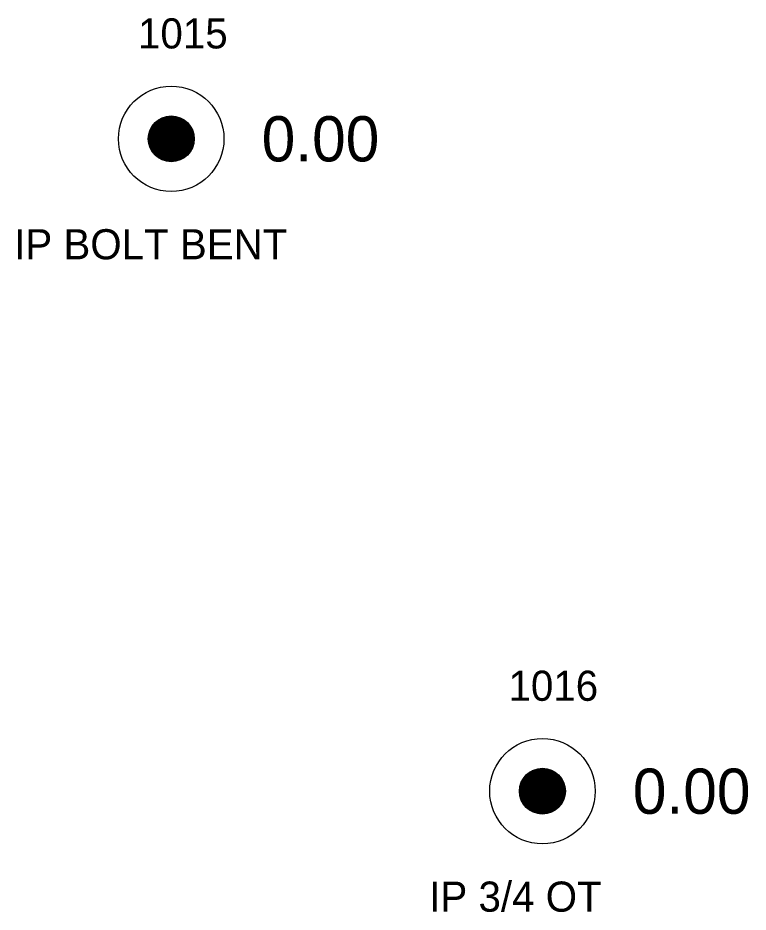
# Model space of a CAD drawing. Extents: x 1538847 to 1546108, y 887169 to 888935.
# Drawn here: x 1538846.5 to 1538870.74, y 887506.13 to 887535.81 of the extents above; entities that cross this region are included whole.
import ezdxf

# ---------------------------------------------------------------- set-up
doc = ezdxf.new("R2010")
doc.units = 0
for name, color, linetype in [('RD_EX_DV_Prop_txCode', 7, 'Continuous'), ('RD_EX_DV_PropPin', 7, 'Continuous'), ('RD_EX_TX_DV_Prop_ELEV', 7, 'Continuous'), ('RD_SMD_Locator', 7, 'Continuous')]:
    doc.layers.add(name, color=color, linetype=linetype)

msp = doc.modelspace()

# ---------------------------------------------------------------- linework, layer by layer
at = {"layer": 'RD_EX_DV_PropPin'}
for p, q in [((1538851.278, 887531.103), (1538851.278, 887532.488)), ((1538851.313, 887531.088), (1538851.313, 887532.503)), ((1538851.348, 887531.075), (1538851.348, 887532.516)), ((1538851.383, 887531.064), (1538851.383, 887532.527)), ((1538851.418, 887531.055), (1538851.418, 887532.536)), ((1538851.453, 887531.047), (1538851.453, 887532.544)), ((1538851.488, 887531.042), (1538851.488, 887532.549)), ((1538851.523, 887531.038), (1538851.523, 887532.553)), ((1538851.558, 887531.035), (1538851.558, 887532.556)), ((1538851.593, 887531.034), (1538851.593, 887532.557)), ((1538851.628, 887531.035), (1538851.628, 887532.556)), ((1538851.664, 887531.038), (1538851.664, 887532.553)), ((1538851.699, 887531.042), (1538851.699, 887532.549)), ((1538851.734, 887531.047), (1538851.734, 887532.544)), ((1538851.769, 887531.055), (1538851.769, 887532.536)), ((1538851.804, 887531.064), (1538851.804, 887532.527)), ((1538851.839, 887531.075), (1538851.839, 887532.516)), ((1538851.874, 887531.088), (1538851.874, 887532.503)), ((1538851.909, 887531.103), (1538851.909, 887532.488)), ((1538850.963, 887531.369), (1538850.963, 887532.222)), ((1538850.998, 887531.321), (1538850.998, 887532.27)), ((1538851.033, 887531.28), (1538851.033, 887532.311)), ((1538851.068, 887531.245), (1538851.068, 887532.346)), ((1538851.103, 887531.213), (1538851.103, 887532.378)), ((1538851.138, 887531.186), (1538851.138, 887532.405)), ((1538851.173, 887531.161), (1538851.173, 887532.43)), ((1538851.208, 887531.139), (1538851.208, 887532.452)), ((1538851.243, 887531.12), (1538851.243, 887532.471)), ((1538851.944, 887531.12), (1538851.944, 887532.471)), ((1538851.979, 887531.139), (1538851.979, 887532.452)), ((1538852.014, 887531.161), (1538852.014, 887532.43)), ((1538852.049, 887531.186), (1538852.049, 887532.405)), ((1538852.084, 887531.213), (1538852.084, 887532.378)), ((1538852.119, 887531.245), (1538852.119, 887532.346)), ((1538852.154, 887531.28), (1538852.154, 887532.311)), ((1538852.189, 887531.321), (1538852.189, 887532.27)), ((1538852.224, 887531.369), (1538852.224, 887532.222)), ((1538850.858, 887531.599), (1538850.858, 887531.992)), ((1538850.893, 887531.498), (1538850.893, 887532.093)), ((1538850.928, 887531.426), (1538850.928, 887532.165)), ((1538852.259, 887531.426), (1538852.259, 887532.165)), ((1538852.294, 887531.498), (1538852.294, 887532.093)), ((1538852.329, 887531.599), (1538852.329, 887531.992)), ((1538863.56, 887509.465), (1538863.56, 887510.817)), ((1538863.595, 887509.448), (1538863.595, 887510.834)), ((1538863.63, 887509.433), (1538863.63, 887510.849)), ((1538863.665, 887509.421), (1538863.665, 887510.861)), ((1538863.7, 887509.41), (1538863.7, 887510.872)), ((1538863.735, 887509.4), (1538863.735, 887510.882)), ((1538863.77, 887509.393), (1538863.77, 887510.889)), ((1538863.805, 887509.387), (1538863.805, 887510.895)), ((1538863.84, 887509.383), (1538863.84, 887510.899)), ((1538863.875, 887509.381), (1538863.875, 887510.901)), ((1538863.91, 887509.38), (1538863.91, 887510.902)), ((1538863.945, 887509.381), (1538863.945, 887510.901)), ((1538863.98, 887509.383), (1538863.98, 887510.899)), ((1538864.015, 887509.387), (1538864.015, 887510.895)), ((1538864.05, 887509.393), (1538864.05, 887510.889)), ((1538864.085, 887509.4), (1538864.085, 887510.882)), ((1538864.12, 887509.41), (1538864.12, 887510.872)), ((1538864.155, 887509.421), (1538864.155, 887510.861)), ((1538864.19, 887509.433), (1538864.19, 887510.849)), ((1538864.225, 887509.448), (1538864.225, 887510.834)), ((1538864.26, 887509.465), (1538864.26, 887510.817)), ((1538863.245, 887509.771), (1538863.245, 887510.511)), ((1538863.28, 887509.714), (1538863.28, 887510.568)), ((1538863.315, 887509.667), (1538863.315, 887510.615)), ((1538863.35, 887509.626), (1538863.35, 887510.656)), ((1538863.385, 887509.59), (1538863.385, 887510.692)), ((1538863.42, 887509.559), (1538863.42, 887510.723)), ((1538863.455, 887509.531), (1538863.455, 887510.751)), ((1538863.49, 887509.506), (1538863.49, 887510.776)), ((1538863.525, 887509.485), (1538863.525, 887510.797)), ((1538864.295, 887509.485), (1538864.295, 887510.797)), ((1538864.33, 887509.506), (1538864.33, 887510.776)), ((1538864.365, 887509.531), (1538864.365, 887510.751)), ((1538864.4, 887509.559), (1538864.4, 887510.723)), ((1538864.435, 887509.59), (1538864.435, 887510.692)), ((1538864.47, 887509.626), (1538864.47, 887510.656)), ((1538864.505, 887509.667), (1538864.505, 887510.615)), ((1538864.54, 887509.714), (1538864.54, 887510.568)), ((1538864.575, 887509.771), (1538864.575, 887510.511)), ((1538863.175, 887509.945), (1538863.175, 887510.337)), ((1538863.21, 887509.843), (1538863.21, 887510.439)), ((1538864.61, 887509.843), (1538864.61, 887510.439)), ((1538864.645, 887509.945), (1538864.645, 887510.337))]:
    msp.add_line(p, q, dxfattribs=at)
for centre, radius in [((1538851.593, 887531.795), 1.75), ((1538851.593, 887531.795), 0.761), ((1538863.91, 887510.141), 1.75), ((1538863.91, 887510.141), 0.761)]:
    msp.add_circle(centre, radius, dxfattribs=at)
at = {"layer": 'RD_SMD_Locator'}
for centre in [(1538851.594, 887531.795), (1538863.91, 887510.141)]:
    msp.add_circle(centre, 0.15, dxfattribs=at)

# ---------------------------------------------------------------- texts
at = {"layer": 'RD_EX_DV_Prop_txCode'}
for s, p in [('1015', (1538850.491, 887534.796)), ('IP BOLT BENT', (1538846.381, 887527.796)), ('1016', (1538862.784, 887513.141)), ('IP 3/4 OT', (1538860.154, 887506.141))]:
    msp.add_text(s, height=1, dxfattribs=at).set_placement(p)
at = {"layer": 'RD_EX_TX_DV_Prop_ELEV'}
for p in [(1538854.594, 887531.046), (1538866.91, 887509.391)]:
    msp.add_text('0.00', height=1.5, dxfattribs=at).set_placement(p)

doc.saveas('drawing.dxf')
